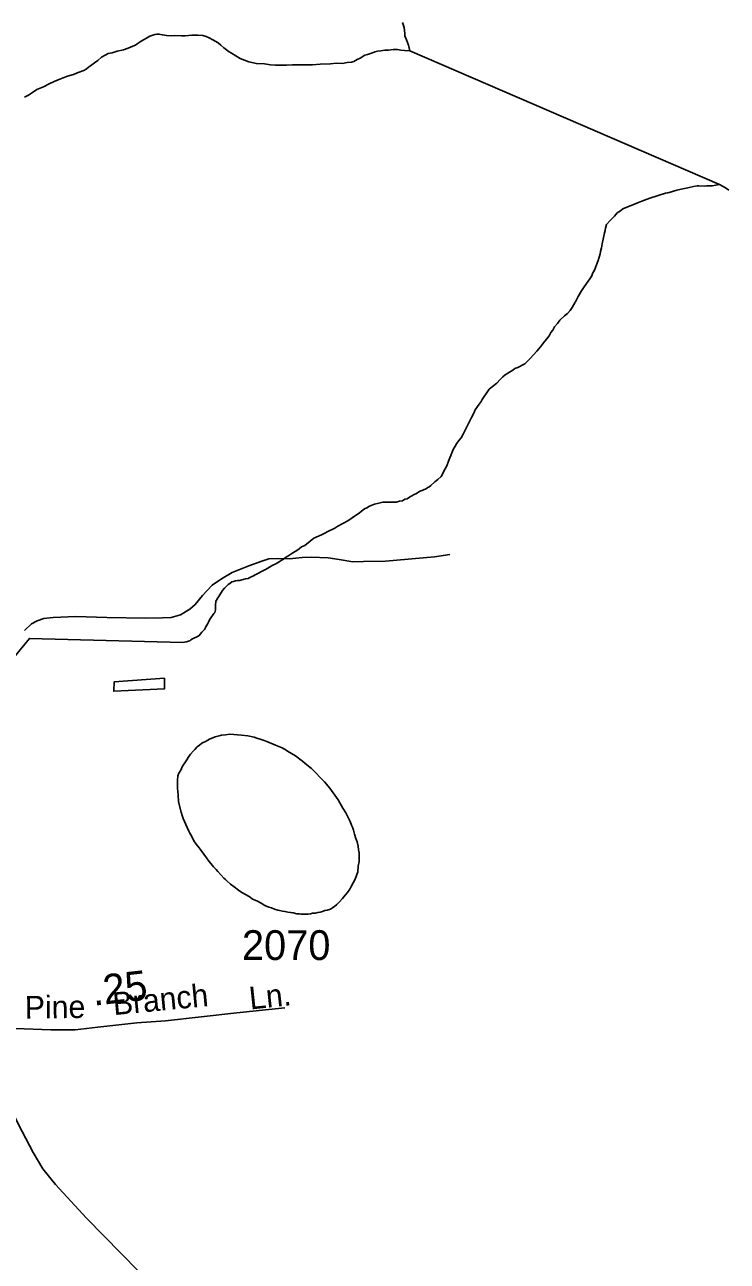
# Model space of a CAD drawing. Extents: x 2206922 to 2357709, y 510027 to 673830.
# Drawn here: x 2302060 to 2305011, y 547579 to 552773 of the extents above; entities that cross this region are included whole.
import ezdxf

# ---------------------------------------------------------------- set-up
doc = ezdxf.new("R2010")
doc.units = 0
for name, color, linetype in [('Exist Hydrographic Creek Single Shore', 7, 'Continuous'), ('Exist Hydrographic Misc Water Feature', 7, 'Continuous'), ('Exist Road Non-System Type 51', 7, 'Continuous'), ('Exist Road Non-System Type 51 Label', 7, 'Continuous'), ('Exist Road Secondary Mileage Hundredths English Label', 7, 'Continuous'), ('Exist Road Secondary Type 51 Attributed', 7, 'Continuous'), ('Exist Road Secondary Type 51 Number Label', 7, 'Continuous')]:
    doc.layers.add(name, color=color, linetype=linetype)

msp = doc.modelspace()

# ---------------------------------------------------------------- linework, layer by layer
at = {"layer": 'Exist Hydrographic Creek Single Shore'}
for points in [[(2302162.6, 552525.3), (2302184.1, 552535.4), (2302200.5, 552541.4), (2302221.9, 552549.6), (2302240.3, 552557.8), (2302264.3, 552564.3), (2302283.8, 552572.3), (2302307.8, 552580.5), (2302317.6, 552586.7), (2302327.7, 552594.9), (2302335.9, 552601), (2302341.6, 552605), (2302353.1, 552613), (2302367.6, 552623.4), (2302383, 552637.3), (2302397.2, 552645.7), (2302410.9, 552651.7), (2302426.9, 552655.8), (2302448.8, 552662.2), (2302474.9, 552668.4), (2302494.6, 552674.4), (2302514.7, 552682.7), (2302524.7, 552686.9), (2302532.3, 552693.1), (2302544.6, 552700.9), (2302558.3, 552709.4), (2302571.9, 552717.5), (2302586, 552725.5), (2302606.3, 552731.8), (2302616, 552734), (2302624, 552734), (2302638.3, 552730.2), (2302656.2, 552728.3), (2302675.8, 552726.6), (2302687.7, 552728.5), (2302718.1, 552727.1), (2302733.9, 552727.2), (2302761.8, 552729.5), (2302787.8, 552729.6), (2302807.9, 552727.8), (2302821.6, 552724.1), (2302834.3, 552718.1), (2302850.1, 552710.5), (2302872.5, 552696.6), (2302884.4, 552686.7), (2302896.3, 552676.8), (2302918.4, 552659.2), (2302928.5, 552653.2), (2302964.8, 552631.6), (2303000.8, 552618), (2303033.2, 552610.3), (2303066.9, 552608.9), (2303093.1, 552605), (2303113.2, 552603.2), (2303159.1, 552603.5), (2303185.2, 552604.1), (2303219.2, 552604.2), (2303249, 552604.6), (2303269.1, 552604.9), (2303300.8, 552607.4), (2303344.9, 552609.6), (2303368.7, 552612.1), (2303394.8, 552610.2), (2303414.6, 552614.5), (2303432.9, 552616.6), (2303442.5, 552618.9), (2303456.7, 552626.8), (2303468.8, 552633.2), (2303488.7, 552645.1), (2303500.6, 552647.5), (2303520.5, 552655.3), (2303530.1, 552659.6), (2303542, 552661.9), (2303555.9, 552663.8), (2303572.1, 552666.3), (2303588.1, 552666.3), (2303608.2, 552668.5), (2303626.1, 552668.7), (2303640.2, 552667), (2303656, 552665), (2303678.3, 552663.2), (2304979.4, 552101.6)], [(2302059, 552468.3), (2302075.2, 552478), (2302093.1, 552488.3), (2302110.9, 552500.6), (2302138.8, 552513), (2302162.6, 552525.3)], [(2304078.2, 551302.2), (2304096.4, 551314.4), (2304110, 551322.5), (2304118.4, 551328.6), (2304132.1, 551333), (2304140.1, 551337.1), (2304150.2, 551343.3), (2304161.6, 551349.2), (2304174, 551361.2), (2304183.6, 551371.5), (2304211.7, 551401.7), (2304227.1, 551419.7), (2304235.3, 551431.8), (2304245.1, 551444.1), (2304253.1, 551454.3), (2304262.7, 551466.2), (2304270.3, 551480.5), (2304278.3, 551490.2), (2304286.1, 551504.4), (2304298.2, 551518.4), (2304307.9, 551532.8), (2304327.9, 551550.9), (2304339.6, 551560.8), (2304351.1, 551573.3), (2304359.5, 551585), (2304367.1, 551597.3), (2304376.7, 551615.3), (2304385.2, 551631.5), (2304398.9, 551655.4), (2304410.6, 551671.9), (2304434, 551706), (2304442, 551718.2), (2304445.9, 551728.2), (2304453.6, 551742), (2304461.6, 551764.3), (2304469.2, 551782.2), (2304472.9, 551796.3), (2304476.8, 551810.3), (2304478.5, 551820.2), (2304483, 551836.5), (2304486.5, 551852.6), (2304495.9, 551898.7), (2304497.9, 551908.5), (2304499.6, 551918.4), (2304503.5, 551934.4), (2304519.5, 551950.7), (2304537.3, 551969), (2304549, 551983.1), (2304563.1, 551991.1), (2304572.6, 551999.4), (2304638.6, 552026), (2304652.3, 552032), (2304686.2, 552044.3), (2304751.8, 552065.3), (2304762, 552067.4), (2304777.8, 552071.5), (2304785.8, 552073.6), (2304799.8, 552077.6), (2304817.4, 552081.8), (2304845.7, 552088.1), (2304869.7, 552094.2), (2304885.5, 552096.7), (2304891.4, 552096.6), (2304915.6, 552094.9), (2304925.5, 552097.1), (2304935.5, 552096.8), (2304947.6, 552097), (2304979.4, 552101.6)], [(2304979.4, 552101.6), (2305003.8, 552087.8), (2305017.9, 552078)], [(2302930.3, 550432.4), (2302936.7, 550434.7), (2302944.7, 550436.7), (2302954.3, 550438.9), (2302964.1, 550439.1), (2302972.1, 550441.1), (2302988.1, 550445.2), (2302998.4, 550447.3), (2303006.2, 550451.4), (2303018.3, 550457.3), (2303030.4, 550463.6), (2303041.9, 550469.5), (2303054, 550475.9), (2303065.6, 550481.8), (2303074.1, 550486.2), (2303081.8, 550489.9), (2303087.8, 550494.3), (2303101.7, 550502.3), (2303111.4, 550506.6), (2303121.8, 550512.7), (2303129.2, 550516.8), (2303137.4, 550522.5), (2303147.5, 550528.7), (2303155.7, 550534.8), (2303165.1, 550541), (2303177.2, 550549), (2303186.6, 550555.2), (2303192.8, 550559.2), (2303198.7, 550561.5), (2303212.9, 550571.6), (2303222.7, 550579.8), (2303236.9, 550585.8), (2303258.6, 550604), (2303274.2, 550616.3), (2303306.4, 550630.5), (2303317.9, 550636.4), (2303333.6, 550644.6), (2303362.2, 550659), (2303375.7, 550667.1), (2303395.8, 550677.4), (2303417.3, 550689.6), (2303435.6, 550701.9), (2303453.2, 550713.8), (2303465.3, 550722.1), (2303475.1, 550730.4), (2303487, 550740.3), (2303497.1, 550744.5), (2303508.6, 550750.5), (2303528.7, 550758.8), (2303546.9, 550763), (2303564.9, 550767.1), (2303620.3, 550767.7), (2303634.7, 550771.6), (2303646.4, 550773.9), (2303656.4, 550780.1), (2303666.4, 550782.3), (2303676.1, 550788.1), (2303685.9, 550794.3), (2303696.4, 550800.4), (2303706.4, 550804.7), (2303715.9, 550810.5), (2303723.9, 550815), (2303729.6, 550817), (2303738, 550821), (2303743.8, 550822.9), (2303753.8, 550829.1), (2303757.5, 550831), (2303765.7, 550837.1), (2303783.3, 550853.5), (2303795.2, 550863.5), (2303809.2, 550875.5), (2303815.1, 550885.6), (2303820.9, 550897.7), (2303832.7, 550919.8), (2303840.7, 550940.1), (2303846.5, 550953.9), (2303850.2, 550964.2), (2303854.1, 550974.2), (2303859.8, 550988.3), (2303867.6, 551002.2), (2303874, 551012.2), (2303883.6, 551026.5), (2303893.6, 551038.4), (2303901.4, 551052.6), (2303907.4, 551064.7), (2303928.9, 551106.9), (2303936.5, 551122.8), (2303946.3, 551141.1), (2303952.1, 551154.9), (2303969.7, 551179.4), (2303977.7, 551191.2), (2303981.6, 551199.5), (2303989.6, 551211.3), (2303999.7, 551225.6), (2304011.1, 551241.7), (2304025.1, 551253.8), (2304042.7, 551268.2), (2304056.7, 551282.3), (2304068.8, 551294.3), (2304078.2, 551302.2)], [(2301773.8, 549824.3), (2302079.5, 550195.5), (2302723.6, 550178.5), (2302737.6, 550180.4), (2302753.1, 550184.6), (2302757.2, 550188.8), (2302765, 550192.9), (2302785.1, 550203.3), (2302792.9, 550207), (2302804.6, 550221.4), (2302814.7, 550233.3), (2302820.6, 550243.3), (2302828.6, 550257.6), (2302832.1, 550263.5), (2302836.4, 550273.4), (2302844.2, 550285.6), (2302848.3, 550291.5), (2302853.8, 550299.6), (2302857.9, 550303.8), (2302859.8, 550310), (2302861.6, 550315.9), (2302861.4, 550319.9), (2302861.6, 550328), (2302861.6, 550333.7)]]:
    msp.add_lwpolyline(points, dxfattribs=at)
at = {"layer": 'Exist Hydrographic Misc Water Feature'}
for points in [[(2303647.2, 552782.7), (2303653.3, 552761.1), (2303655.2, 552749.1), (2303657.4, 552737), (2303657.4, 552726.8), (2303659.5, 552719.2), (2303663.8, 552709.2), (2303672, 552687.3), (2303678.3, 552663.2)], [(2302861.6, 550333.7), (2302863.3, 550351.7), (2302865.3, 550355.8), (2302871.3, 550365.9), (2302875.2, 550371.8), (2302879.3, 550378.1), (2302891.1, 550396.1), (2302898.7, 550406.3), (2302904.5, 550412.4), (2302914.7, 550422.2), (2302920.9, 550426.5), (2302930.3, 550432.4)], [(2302435.1, 550013.5), (2302647.1, 550027.8), (2302647.3, 549983.6), (2302433.7, 549973.6), (2302435.1, 550013.5)], [(2302903.9, 549183), (2302895.9, 549188.6), (2302871.7, 549216.6), (2302863.7, 549224.3), (2302853.2, 549236.4), (2302841.1, 549250), (2302832.9, 549260.1), (2302822.9, 549273.8), (2302800.7, 549303.9), (2302792.9, 549315.7), (2302780.2, 549331.4), (2302770.2, 549345.5), (2302762.2, 549363.3), (2302753.8, 549377.1), (2302749.7, 549385), (2302741.7, 549401.2), (2302725.1, 549439), (2302721.2, 549450.9), (2302717.1, 549464.9), (2302706.4, 549508.7), (2302704.1, 549538.7), (2302702.1, 549566.5), (2302701.9, 549572.7), (2302701.5, 549588.5), (2302701.9, 549598.6), (2302703.5, 549618.6), (2302707.2, 549628.6), (2302715.2, 549642.5), (2302723, 549658.7), (2302732.4, 549672.7), (2302740.4, 549684.9), (2302746.4, 549694.9), (2302756.4, 549709.2), (2302768.1, 549721.3), (2302774.3, 549729.3), (2302783.9, 549739.2), (2302793.7, 549747.4), (2302803.6, 549755.7), (2302821.6, 549763.9), (2302835.8, 549771.9), (2302859.6, 549782.1), (2302877.2, 549786.3), (2302887.2, 549788.5)], [(2302887.2, 549788.5), (2302903.4, 549790.5), (2302921.3, 549792.7), (2302971.1, 549789.2), (2302997.4, 549785.7), (2303023.2, 549779.8), (2303035.3, 549775.9), (2303049.4, 549772.2), (2303061.7, 549768.3), (2303077.7, 549762.6), (2303113.8, 549747), (2303141.9, 549735.1), (2303157.7, 549725.5), (2303163.9, 549721.3), (2303180.1, 549711.5), (2303198.1, 549701.9), (2303216.2, 549688.2), (2303226.4, 549680.2), (2303238.3, 549670.4), (2303264.5, 549648.6), (2303319.5, 549593.3), (2303341.6, 549565.6), (2303376.1, 549517.8), (2303396.6, 549481.9), (2303408.5, 549462.2), (2303418.9, 549442.4), (2303426.7, 549426.2), (2303433.1, 549410.3), (2303437.2, 549402.4), (2303441.3, 549390.4), (2303445.4, 549372.7), (2303451.3, 549354.8), (2303455.9, 549340.7), (2303460.2, 549322.7), (2303462.2, 549307), (2303464.5, 549294.9), (2303464.9, 549277), (2303464.9, 549258.7), (2303461, 549239), (2303459.1, 549214.9), (2303447.9, 549184.6), (2303439.7, 549168.8), (2303429.8, 549150.4), (2303425.9, 549142.5), (2303415.9, 549128.6), (2303406.2, 549116.3), (2303394.5, 549102.2), (2303382.9, 549088.2), (2303370.6, 549077.9), (2303362.8, 549070.1), (2303352.9, 549063.9), (2303345.1, 549057.8), (2303331.2, 549053.4), (2303321.1, 549051.7), (2303311.1, 549047.5), (2303300.8, 549045.4), (2303291.2, 549043.2), (2303281.2, 549041.1), (2303269.1, 549040.8), (2303261.1, 549038.7), (2303249.4, 549036.5), (2303239.5, 549036.7), (2303231.3, 549036.3), (2303221.3, 549036.3), (2303213.1, 549038.3), (2303203.2, 549038.2), (2303187.2, 549042.2), (2303177, 549044.1), (2303165.1, 549045.9), (2303153.4, 549047.7), (2303143.2, 549049.7), (2303137, 549051.4), (2303122.9, 549053.5), (2303109.1, 549057.2), (2303097.2, 549063), (2303085.1, 549066.9), (2303068.7, 549073), (2303052.9, 549082.7), (2303035.1, 549092.3), (2303016.8, 549100.3), (2303006.6, 549107.9), (2302990.8, 549118), (2302972.6, 549127.6), (2302958.4, 549137.5), (2302940.2, 549151.2), (2302924, 549163.3), (2302909.6, 549176.8), (2302903.9, 549183)]]:
    msp.add_lwpolyline(points, dxfattribs=at)
at = {"layer": 'Exist Road Non-System Type 51'}
msp.add_lwpolyline([(2302058.8, 550228.7), (2302087.7, 550255.9), (2302111.7, 550268.7), (2302140.5, 550278.3), (2302179, 550283.2), (2302275.1, 550288), (2302404.9, 550283.2), (2302568.3, 550279.9), (2302638.8, 550281.6), (2302675.7, 550283.2), (2302714.1, 550294.4), (2302754.2, 550318.4), (2302776.6, 550337.7), (2302807, 550376.1), (2302847.1, 550419.4), (2302887.1, 550445.1), (2302932, 550472.3), (2303000.9, 550499.6), (2303055.4, 550520.4), (2303085.8, 550530), (2303121.1, 550531.6), (2303172.3, 550530), (2303225.2, 550534.8), (2303263.7, 550536.4), (2303334.1, 550533.2), (2303380.6, 550526.8), (2303438.3, 550517.2), (2303483.2, 550518.8), (2303576.1, 550520.4), (2303781.2, 550538), (2303845.2, 550547.7)], dxfattribs=at)
at = {"layer": 'Exist Road Secondary Type 51 Attributed'}
for points in [[(2301828.1, 548577.5), (2301983.4, 548558.7), (2302169.3, 548550.6), (2302271.3, 548551.7), (2302367.1, 548562.8), (2302531.5, 548580.7), (2302651.6, 548588.7), (2302951.2, 548622.4), (2303153.1, 548643.2)], [(2305052.4, 544911.7), (2304951.5, 544979), (2304839.8, 545055.8), (2304740.2, 545128.5), (2304640.6, 545218.7), (2304550.4, 545307.6), (2304411.8, 545466.5), (2304262.4, 545637.5), (2304063.2, 545859.7), (2303280.2, 546737.3), (2302937.7, 547105), (2302772.1, 547269.2), (2302617.3, 547428.2), (2302537.9, 547537.1), (2302320, 547759.9), (2302188.6, 547901), (2302135.7, 547966.5), (2302095.7, 548035.7), (2302049.8, 548124.2), (2302004.3, 548212), (2301828.1, 548577.5)]]:
    msp.add_lwpolyline(points, dxfattribs=at)

# ---------------------------------------------------------------- texts
at = {"layer": 'Exist Road Non-System Type 51 Label'}
for s, rotation, p in [('Branch', 5.4954, (2302434.2, 548612.5)), ('Pine', 0.6174, (2302060.6, 548598.2)), ('Ln.', 6.0853, (2303007.5, 548636.2))]:
    msp.add_text(s, height=95, rotation=rotation, dxfattribs=at).set_placement(p)
at = {"layer": 'Exist Road Secondary Mileage Hundredths English Label'}
msp.add_text('.25', height=125, rotation=6.4993, dxfattribs=at).set_placement((2302349.4, 548652))
at = {"layer": 'Exist Road Secondary Type 51 Number Label'}
msp.add_text('2070', height=125, dxfattribs=at).set_placement((2302972.4, 548844.4))

doc.saveas('drawing.dxf')
